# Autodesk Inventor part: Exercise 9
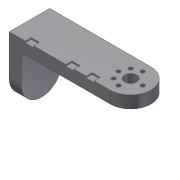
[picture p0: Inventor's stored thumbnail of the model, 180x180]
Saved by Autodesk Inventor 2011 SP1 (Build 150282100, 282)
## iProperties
Created: 2011-02
Part Number: Exercise 9
Document SubType Name: Modeling
Designer: SERGIO
Density: 1 g/cm^3
Author: SERGIO
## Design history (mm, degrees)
sketch "Sketch1"
  geometry: L1 (-30, -30)-(-300, -30); L2 (-300, -30)-(-300, 0); L3 (-300, 0)-(0, 0); L4 (-30, -30)-(-30, -150); L5 (-30, -150)-(0, -150); L6 (0, -150)-(0, 0); 1 further point
  constraints: 12 end point, 3 parallel, 3 perpendicular, 1 coincident, 1 horizontal
  dimensions: "d1" = 30 distance of L1.end L2.end; "d24" = 300 distance of L2.end L3.end; "d25" = 150 distance of L5.end L3.end
extrude "Extrusion1" new body sketch "Sketch1" stored distance "d3" = 100; taper "d4" = 0 deg
fillet "Fillet1"
sketch "Sketch3"
  geometry: A1 r 50 centre (250, 50) between (250, 0) and (250, 100) reference; 1 further point
hole "Hole2" sketch "Sketch3" at (250, 50) diameter "Dia_Hole2" = 30 (= Dia_Hole1); stored, may be unused: countersink angle "d16" = 90 deg, drill point angle "d18" = 118 deg; dims "d13" = 6, "d14" = 4, "d15" = 2, "d17" = 8
fillet "Fillet3"
sketch "Sketch5" dims "d26" = 60
  geometry: C1 r 15 at (250, 50) reference; C2 r 5 at (280, 50); A1 r 50 centre (250, 50) between (250, 0) and (250, 100) reference; 2 further points
  constraints: 2 horizontal alignment, 1 centre point, 1 coincident, 2 other
  dimensions: "d27" = 10 diameter of C2
extrude "Extrusion2" cut sketch "Sketch5" stored distance "d28" = 10; taper "d29" = 0 deg
pattern_circular "Circular Pattern1" dims angle "d31" = 360 deg
sketch "Sketch6"
  geometry: L1 (0, 0)-(0, 100) reference; L2 (0, 0)-(250, 0) reference; L3 (40, 0)-(60, 0); L4 (60, 0)-(60, 15); L5 (60, 15)-(40, 15); L6 (40, 15)-(40, 0); 1 further point
  constraints: 8 end point, 2 parallel, 1 horizontal, 1 perpendicular, 1 point on line
  dimensions: "d33" = 250 distance of L1.start L2.end (derived); "d34" = 20 distance of L5.end L4.end; "d35" = 15 distance of L4.end L3.end; "d36" = 40 distance between parallel lines of L1 L6
extrude "Extrusion3" cut sketch "Sketch6" distance "d37" = 4; taper "d38" = 0 deg
pattern_linear "Rectangular Pattern1" dims "d41" = 50
body "Solid1"
other parameters: "Dia_Hole1" = 30
